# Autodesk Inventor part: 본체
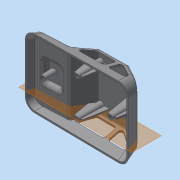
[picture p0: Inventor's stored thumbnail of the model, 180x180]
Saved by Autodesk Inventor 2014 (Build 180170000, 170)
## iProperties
Created: 2015-05
Part Number: 본체
Material: 일반
Document SubType Name: Modeling
Designer: dgall
Density: 1 g/cm^3
Appearance: 기본값
Author: dgall
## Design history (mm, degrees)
sketch "스케치1"
  geometry: L1 (-61, 0)-(61, 0); L2 (-61, 0)-(-61, 9); L3 (-61, 0)-(-58.588, 9); L4 (-61, 9)-(-19, 9); L5 (61, 0)-(31, 0); L6 (31, 0)-(31, 31); L7 (31, 31)-(57.056, 14.718); L8 (61, 0)-(57.056, 14.718); L9 (31, 31)-(-4.605, 31); L10 (-60, -1)-(60, -1); L11 (60, -1)-(60, 0); L12 (-61, 0)-(-60, 0); L13 (-60, 0)-(-60, -1); L14 (-4.605, 31)-(-18.633, 11.094); L15 (-58.588, 9)-(-18.633, 11.094); 2 further points
  constraints: 30 end point, 5 perpendicular, 4 point on line, 1 coincident, 1 horizontal, 1 midpoint, 1 parallel
  dimensions: "d0" = 122 distance of L1.start L1.end; "d3" = 9 distance of L1.start L2.end; "d4" = 75 deg angle of L1 L3; "d6" = 42 distance of L2.end L4.end; "d9" = 30 distance of L1.end L5.end; "d10" = 31 distance of L5.end L6.end; "d12" = 105 deg angle of L1 L8; "d13" = 35.60485 distance of L6.end L9.end; "d16" = 1 distance of L10.end L11.end; "d17" = 1 distance of L1.end L11.end; "d18" = 1 distance of L1.start L12.end; "d19" = 1 distance of L10.start L12.end; "d23" = 24.35241 distance of L9.end L14.end; "d24" = 30.72498 distance of L6.end L7.end; "d25" = 3 deg angle of L4 L15
extrude "돌출2" new body sketch "스케치1" stored distance "d26" = 76; taper "d27" = 0 deg
sketch "스케치2"
  geometry: L1 (0, 76)-(0, 0) reference; L2 (58.037, 38)-(0, 38); L3 (0, 38)-(11, 38); L4 (11, 51)-(11, 25); L5 (11, 51)-(31, 51); L6 (31, 51)-(31, 25); L7 (31, 25)-(11, 25)
  constraints: 12 end point, 3 perpendicular, 2 midpoint, 1 horizontal alignment, 1 point on line
  dimensions: "d29" = 26 distance of L4.start L4.end; "d30" = 11 distance of L2.end L3.end; "d31" = 20 distance of L4.start L5.end; "d32" = 26 distance of L5.end L6.end
extrude "돌출3" join sketch "스케치2" distance "d33" = 5; taper "d34" = 0 deg
fillet "모깎기1" dims "d72" = 3
fillet "모깎기2" dims "d73" = 2.5
sketch "스케치7"
  geometry: L1 (61.661, 76)-(61.661, 0) reference; L2 (65.605, 0)-(61.661, 0) reference; L3 (65.605, 76)-(65.605, 0) reference; L4 (61.661, 76)-(65.605, 76) reference; 3 further points
  constraints: 1 horizontal alignment, 1 midpoint, 1 other
  dimensions: "d74" = 50 distance from line of L3 point (15.605, 38)
  node "투영된 루프3"
feature "면 기울기3" dims angle "d139" = 15 deg
feature "면 기울기4" dims angle "d140" = 15 deg
fillet "모깎기7" dims "d141" = 12
fillet "모깎기8" dims "d142" = 3
fillet "모깎기9" dims "d143" = 2.5
feature "쉘2" dims "d144" = 2
sketch "스케치26"
  geometry: L1 (-3.049, 31)-(30.14, 31) reference; L2 (-17.793, 12.285)-(-5.501, 29.728) reference; L3 (31.73, 30.544)-(45.466, 21.961) reference; L4 (45.466, 21.961)-(56.054, 15.344) reference; L5 (-0.456, 26)-(18.418, 26); L6 (-2.908, 24.728)-(-9.25, 15.728); L7 (-6.798, 11)-(18.418, 11); L8 (21.418, 14)-(21.418, 23); L9 (25.571, 23)-(25.571, 14); L10 (30.296, 25.544)-(44.699, 16.544); L11 (28.571, 11)-(43.109, 11); L12 (28.571, 26)-(28.706, 26); A1 r 3 centre (18.418, 23) between (21.418, 23) and (18.418, 26); A2 r 3 centre (18.418, 14) between (18.418, 11) and (21.418, 14); A3 r 3 centre (-6.798, 14) between (-9.25, 15.728) and (-6.798, 11); A4 r 3 centre (28.571, 23) between (28.571, 26) and (25.571, 23); A5 r 3 centre (28.706, 23) between (30.296, 25.544) and (28.706, 26); A6 r 3 centre (28.571, 14) between (25.571, 14) and (28.571, 11); A7 r 3 centre (43.109, 14) between (43.109, 11) and (44.699, 16.544); A8 r 3 centre (-0.456, 23) between (-0.456, 26) and (-2.908, 24.728); 7 further points
  constraints: 16 end point, 16 point on circle, 16 tangent, 12 point on line, 8 centre point, 6 parallel, 5 equal radius, 2 perpendicular, 1 horizontal alignment
  dimensions: "d145" = 5 distance between parallel lines of L5 L1; "d147" = 5 distance between parallel lines of L2 L6; "d148" = 34 distance of point (-12.582, 11) point (21.418, 11); "d149" = 15 distance of point (21.418, 11) point (21.418, 26); "d150" = 3 radius of A1; "d151" = 5 distance between parallel lines of L10 L4; "d152" = 28 distance of point (25.571, 11) point (53.571, 11); "d153" = 15 distance of point (25.571, 26) point (25.571, 11); "d154" = 3 radius of A4; "d155" = 3 radius of A8
extrude "돌출12" cut sketch "스케치26" stored distance "d156" = 130; taper "d157" = 0 deg
feature "엠보싱2" dims "d0" = 122, "d158" = 0.5, "d159" = 0
sketch "스케치27"
  geometry: L1 (31, 30.583)-(31, -30.583) reference; L2 (29, 30.583)-(29, -30.583) reference; L3 (29, 22)-(29, -22); L4 (0, -28.811)-(0, 28.811) reference; L5 (29, 22)-(0, 22); L6 (29, -22)-(0, -22); L7 (0, 22)-(0, 25); L8 (0, 25)-(29, 26.013); L9 (29, 26.013)-(29, 22); L10 (0, -22)-(0, -25); L11 (0, -25)-(29, -26.013); L12 (29, -26.013)-(29, -22); 2 further points
  constraints: 18 end point, 6 point on line, 3 collinear, 2 midpoint, 2 perpendicular
  dimensions: "d160" = 44 distance of L3.start L3.end; "d161" = 3 distance of L5.end L7.end; "d162" = 2 deg angle of L5 L8; "d163" = 3 distance of L6.end L10.end; "d164" = 2 deg angle of L6 L11
revolve "회전3" stored, may be unused: angle "d165" = 90 deg
revolve "회전4" stored, may be unused: angle "d166" = 90 deg
sketch "스케치28"
  geometry: L1 (-44.765, 12.729)-(-30.784, 13.461) reference; L2 (-3.049, 29)-(-3.049, 29) reference; L3 (-3.866, 28.576)-(-3.866, 28.576) reference; L4 (-3, 0)-(3, 0) reference; L5 (0, 0)-(-40, 0); L6 (-40, 0)-(-40, 12.978); L7 (-40, 0)-(-37, 0); L8 (-37, 0)-(-36.54, 13.16); L9 (-36.54, 13.16)-(-40, 12.978)
  constraints: 10 end point, 3 point on line, 2 collinear, 1 perpendicular, 2 other
  dimensions: "d167" = 40 distance of L5.start L5.end; "d168" = 3 distance of L5.end L7.end; "d169" = 2 deg angle of L6 L8
revolve "회전5" sketch "스케치28" stored, may be unused: angle "d170" = 90 deg
sketch "스케치29"
  geometry: L1 (-3.049, 29)-(-3.049, 29) reference; L2 (-3.866, 28.576)-(-3.866, 28.576) reference; L3 (-3, 0)-(3, 0) reference; L4 (31.73, 30.544)-(45.466, 21.961) reference; L5 (30.67, 28.848)-(44.406, 20.265) reference; L6 (44.406, 20.265)-(54.994, 13.648) reference; L7 (0, 0)-(40, 0); L8 (40, 0)-(40, 23.018); L9 (40, 0)-(37, 0); L10 (37, 0)-(36.111, 25.448)
  constraints: 8 end point, 4 point on line, 1 perpendicular, 2 other
  dimensions: "d171" = 40 distance of L7.start L7.end; "d172" = 3 distance of L7.end L9.end; "d173" = 2 deg angle of L8 L10
revolve "회전6" sketch "스케치29" stored, may be unused: angle "d174" = 90 deg
sketch "스케치31"
  geometry: L1 (31.73, 30.544)-(45.466, 21.961) reference; L2 (39.886, 25.448)-(43.898, 22.94); L3 (39.886, 25.448)-(39.886, 25.448) reference; L4 (39.886, 25.448)-(39.886, 25.448) reference; L5 (39.886, 25.448)-(43.898, 25.448); L6 (43.898, 25.448)-(43.898, 22.94); 1 further point
  constraints: 6 end point, 2 point on line, 1 collinear, 1 horizontal, 1 perpendicular
  dimensions: "d176" = 2.50743 distance of L5.end L2.end
extrude "돌출13" cut sketch "스케치31" stored distance "d177" = 130; taper "d178" = 0 deg
sketch "스케치32"
  geometry: C1 r 3 at (0, 0) reference; C2 r 3 at (40, 22) reference; C3 r 3 at (80, 0) reference; C4 r 3 at (40, -22) reference; 1 further point
hole "구멍1" sketch "스케치32" at (0, 0), (40, -22), (80, 0), (40, 22) diameter "d179" = 3.302; stored, may be unused: countersink angle "d183" = 90 deg, drill point angle "d185" = 118 deg; dims "d180" = 9, "d181" = 4, "d182" = 2, "d184" = 11
sketch "스케치33"
  geometry: L1 (43.723, 20.692)-(36.111, 25.448) reference; L2 (43, 0)-(37, 0) reference; L3 (-36.54, 13.16)-(-43.447, 12.798) reference; L4 (-43, 0)-(-37, 0) reference; L5 (-36.54, 13.16)-(-37, 0) reference; L6 (-43.447, 12.798)-(-43, 0) reference; L7 (37, 0)-(36.111, 25.448) reference; L8 (43, 0)-(43.723, 20.692) reference; L9 (43, 0)-(43, 0); L10 (35, 2)-(37.788, 2); L11 (42.212, 2)-(45, 2); L12 (44.406, 20.265)-(54.994, 13.648) reference; L13 (45, 2)-(47.842, 18.118); L14 (35, 2)-(30.24, 28.995); L15 (42.212, 2)-(37.788, 2); L16 (40, 23.018)-(40, 0); L17 (-3.049, 29)-(30.14, 29) reference; L18 (-45, 2)-(-42.126, 2); L19 (-37.707, 2)-(-35, 2); L20 (-42.126, 2)-(-37.707, 2); L21 (-35, 2)-(-33, 13.345); L22 (-40, 12.978)-(-40, 0); L23 (-45, 2)-(-45.287, 12.701); L24 (-42.126, 2)-(-42.126, 12.867); L25 (-42.126, 12.867)-(-45.287, 12.701); L26 (42.212, 2)-(42.212, 21.636); L27 (42.212, 21.636)-(47.842, 18.118); L28 (37.788, 2)-(37.788, 24.4); L29 (37.788, 24.4)-(30.67, 28.848); L30 (-37.707, 2)-(-37.707, 13.098); L31 (-33, 13.345)-(-37.707, 13.098); A1 r 1 centre (30.14, 28) between (30.67, 28.848) and (30.14, 29) reference; A2 r 0.5 centre (-45.261, 12.202) between (-45.287, 12.701) and (-45.76, 12.221) reference; A3 r 1 centre (30.14, 28) between (30.67, 28.848) and (30.24, 28.995); 6 further points; 1 other entity
  constraints: 42 end point, 8 parallel, 3 midpoint, 3 point on circle, 2 perpendicular, 2 point on line, 2 tangent, 2 vertical alignment, 1 centre point, 1 coincident, 1 collinear, 1 concentric, 12 other
  dimensions: "d189" = 10 distance of L10.start L11.end; "d190" = 2 horizontal distance of L8.start L11.end; "d191" = 2 horizontal distance of L2.end L10.start; "d193" = 10 deg angle of L16 L14; "d194" = 10 deg angle of L13 L16; "d195" = 2 horizontal distance of L9.end L11.end; "d196" = 2 horizontal distance of L2.end L10.start; "d197" = 10 distance of L18.start L19.end; "d198" = 2 horizontal distance of L4.end L19.end; "d199" = 2 horizontal distance of L4.start L18.start; "d200" = 10 deg angle of L22 L21; "d201" = 2 horizontal distance of L4.end L19.end; "d202" = 10.8669 distance of L18.end L24.end; "d203" = 22.39984 distance of L10.end L28.end; "d204" = 19.6358 distance of L11.start L26.end
  node "투영된 루프15"
  node "투영된 루프16"
extrude "돌출14" join sketch "스케치33" stored distance "d206" = 2; taper "d207" = 0 deg
node "작업 평면5"
sketch "스케치35"
  geometry: L1 (-3.866, 28.576)-(-3.866, 28.576) reference; L2 (-3.049, 29)-(-3.049, 29) reference; L3 (3, 0)-(-3, 0) reference; L4 (3, 0)-(4.013, 29) reference; L5 (-3, 0)-(-3.992, 28.398) reference; L6 (4.013, 29)-(-3.049, 29) reference; L7 (-3.049, 29)-(30.14, 29) reference; L8 (-16.159, 11.133)-(-3.866, 28.576) reference; L9 (5, 2)-(9.761, 29); L10 (2.167, 29)-(9.761, 29); L11 (0, 29)-(0, 0); L12 (-4.809, 2)-(-2.082, 2); L13 (2.167, 2)-(5, 2); L14 (2.167, 29)-(2.167, 2); L15 (-4.809, 2)-(-8.368, 22.188); L16 (-2.082, 2)-(-2.082, 29); L17 (-8.368, 22.188)-(-3.992, 28.398); L18 (-2.082, 29)-(-3.049, 29); L19 (-3.992, 28.398)-(-3.049, 29); 2 further points
  constraints: 22 end point, 5 point on line, 3 collinear, 3 perpendicular, 2 parallel, 1 midpoint, 1 vertical alignment, 2 other
  dimensions: "d211" = 2 horizontal distance of L3.start L9.start; "d213" = 10 deg angle of L11 L9; "d214" = 2 vertical distance of L3.end L12.start; "d215" = 2.16705 distance of L10.start L11.start; "d216" = 7.59378 distance of L10.start L9.end; "d217" = 10 deg angle of L11 L15; "d218" = 2.08199 distance of L11.start L16.end; "d219" = 7.59756 distance of L15.end L5.end
extrude "돌출15" join sketch "스케치35" stored distance "d220" = 2; taper "d221" = 0 deg
node "작업 평면6"
sketch "스케치36"
  geometry: L1 (-3.049, 29)-(-3.049, 29) reference; L2 (-3.866, 28.576)-(-3.866, 28.576) reference; L3 (-3, 0)-(3, 0) reference; L4 (4.013, 29)-(3, 0) reference; L5 (-3.992, 28.398)-(-3, 0) reference; L6 (-3.049, 29)-(30.14, 29) reference; L7 (-16.159, 11.133)-(-3.866, 28.576) reference; L8 (-4.929, 2)-(-2.2, 2); L9 (2.189, 2)-(5.071, 2); L10 (0, 0)-(0, 29); L11 (2.189, 2)-(2.189, 29); L12 (5.071, 2)-(9.832, 29); L13 (9.832, 29)-(2.189, 29); L14 (-2.2, 2)-(-2.2, 29); L15 (-4.929, 2)-(-8.465, 22.051); L16 (-8.465, 22.051)-(-3.992, 28.398); L17 (-2.2, 29)-(-3.049, 29); 2 further points
  constraints: 20 end point, 5 point on line, 4 perpendicular, 2 collinear, 2 horizontal, 1 midpoint, 1 vertical alignment, 2 other
  dimensions: "d223" = 10 distance of L8.start L9.end; "d224" = 2 vertical distance of point (0, 0) L9.end; "d225" = 2 vertical distance of L3.start L8.start; "d226" = 10 deg angle of L11 L12; "d227" = 2 distance from line of L4 L9.end; "d228" = 7.64307 distance of L12.end L11.end; "d229" = 10 deg angle of L10 L15; "d230" = 0.84861 distance of L1.end L14.end
extrude "돌출16" join sketch "스케치36" stored distance "d231" = 2; taper "d232" = 0 deg
sketch "스케치8"
  geometry: L1 (14.718, -38)-(14.718, 38) reference; L2 (0, 38)-(14.718, 38) reference; L3 (0, -38)-(0, 38) reference; L4 (14.718, -38)-(0, -38) reference; L5 (-1, -37)-(-1, 37); L6 (-1, -37)-(0, -37); L7 (-1, 37)-(0, 37); 3 further points
  constraints: 6 end point, 2 midpoint, 2 perpendicular, 2 point on line, 1 horizontal alignment, 1 parallel
  dimensions: "d77" = 74 distance of L5.start L5.end; "d78" = 1 horizontal distance of L5.end L2.start
extrude "돌출6" join sketch "스케치8" stored distance "d79" = 120; taper "d80" = 0 deg
sketch "스케치10"
  geometry: L1 (-44.869, 14.726)-(-30.889, 15.459) reference; L2 (-45.287, 12.701)-(-30.262, 13.489); L3 (-50.495, 7.421)-(-24.53, 8.782); A1 r 2.5 centre (-30.236, 12.989) between (-27.761, 13.347) and (-30.366, 15.486) reference; A2 r 3 centre (-50.756, 12.415) between (-50.599, 9.419) and (-47.759, 12.299) reference; A3 r 2.5 centre (-45.261, 12.202) between (-45.391, 14.698) and (-47.759, 12.299) reference; A4 r 3 centre (-24.792, 13.775) between (-27.761, 13.347) and (-24.635, 10.779) reference; A5 r 0.5 centre (-30.236, 12.989) between (-29.741, 13.061) and (-30.262, 13.489); A6 r 5 centre (-24.792, 13.775) between (-29.741, 13.061) and (-24.53, 8.782); A7 r 5 centre (-50.756, 12.415) between (-50.495, 7.421) and (-45.76, 12.221); A8 r 0.5 centre (-45.261, 12.202) between (-45.287, 12.701) and (-45.76, 12.221); 1 further point
  constraints: 8 point on circle, 4 centre point, 4 end point, 2 tangent, 1 parallel, 2 other
  dimensions: "d91" = 2 radial gap between concentric circles of A4 A6; "d93" = 2 radial gap between concentric circles of A2 A7; "d94" = 2 distance between parallel lines of L2 L1
extrude "돌출8" cut sketch "스케치10" stored distance "d95" = 22; taper "d96" = 0 deg
feature "면 기울기1" dims angle "d112" = 15 deg
feature "면 기울기2" dims angle "d113" = 15 deg
sketch "스케치19"
  geometry: L1 (-18.633, 11.094)-(-4.605, 31) reference; L2 (-4.605, 31)-(31, 31) reference; L3 (31, 31)-(57.056, 14.718) reference; L4 (57.056, 14.718)-(61, 0) reference; L5 (-2.908, 24.728)-(-9.25, 15.728); L6 (-0.456, 26)-(18.418, 26); L7 (-6.798, 11)-(18.418, 11); L8 (21.418, 14)-(21.418, 23); L9 (25.571, 23)-(25.571, 14); L10 (30.296, 25.544)-(44.699, 16.544); L11 (28.571, 26)-(28.706, 26); L12 (28.571, 11)-(43.109, 11); A1 r 3 centre (18.418, 23) between (21.418, 23) and (18.418, 26); A2 r 3 centre (18.418, 14) between (18.418, 11) and (21.418, 14); A3 r 3 centre (-6.798, 14) between (-9.25, 15.728) and (-6.798, 11); A4 r 3 centre (-0.456, 23) between (-0.456, 26) and (-2.908, 24.728); A5 r 3 centre (28.571, 23) between (28.571, 26) and (25.571, 23); A6 r 3 centre (28.706, 23) between (30.296, 25.544) and (28.706, 26); A7 r 3 centre (28.571, 14) between (25.571, 14) and (28.571, 11); A8 r 3 centre (43.109, 14) between (43.109, 11) and (44.699, 16.544); 6 further points
  constraints: 16 end point, 16 point on circle, 16 tangent, 10 point on line, 8 centre point, 6 equal radius, 6 parallel, 2 perpendicular, 1 horizontal alignment
  dimensions: "d114" = 5 distance between parallel lines of L1 L5; "d115" = 5 distance between parallel lines of L6 L2; "d116" = 15 distance of point (21.418, 11) point (21.418, 26); "d117" = 34 distance of point (21.418, 11) point (-12.582, 11); "d118" = 3 radius of A1; "d119" = 5 distance between parallel lines of L10 L3; "d120" = 5 distance between parallel lines of L11 L2; "d121" = 28 distance of point (53.571, 11) point (25.571, 11); "d122" = 3 radius of A5
extrude "돌출10" cut sketch "스케치19" stored distance "d123" = 130; taper "d124" = 0 deg
node "솔리드2"
node "투영된 루프4"
node "투영된 루프10"
node "투영된 루프11"
node "투영된 루프12"
node "투영된 루프13"
node "투영된 루프14"
node "투영된 루프18"
node "투영된 루프19"
other parameters: "d208" = 22, "d222" = -22
